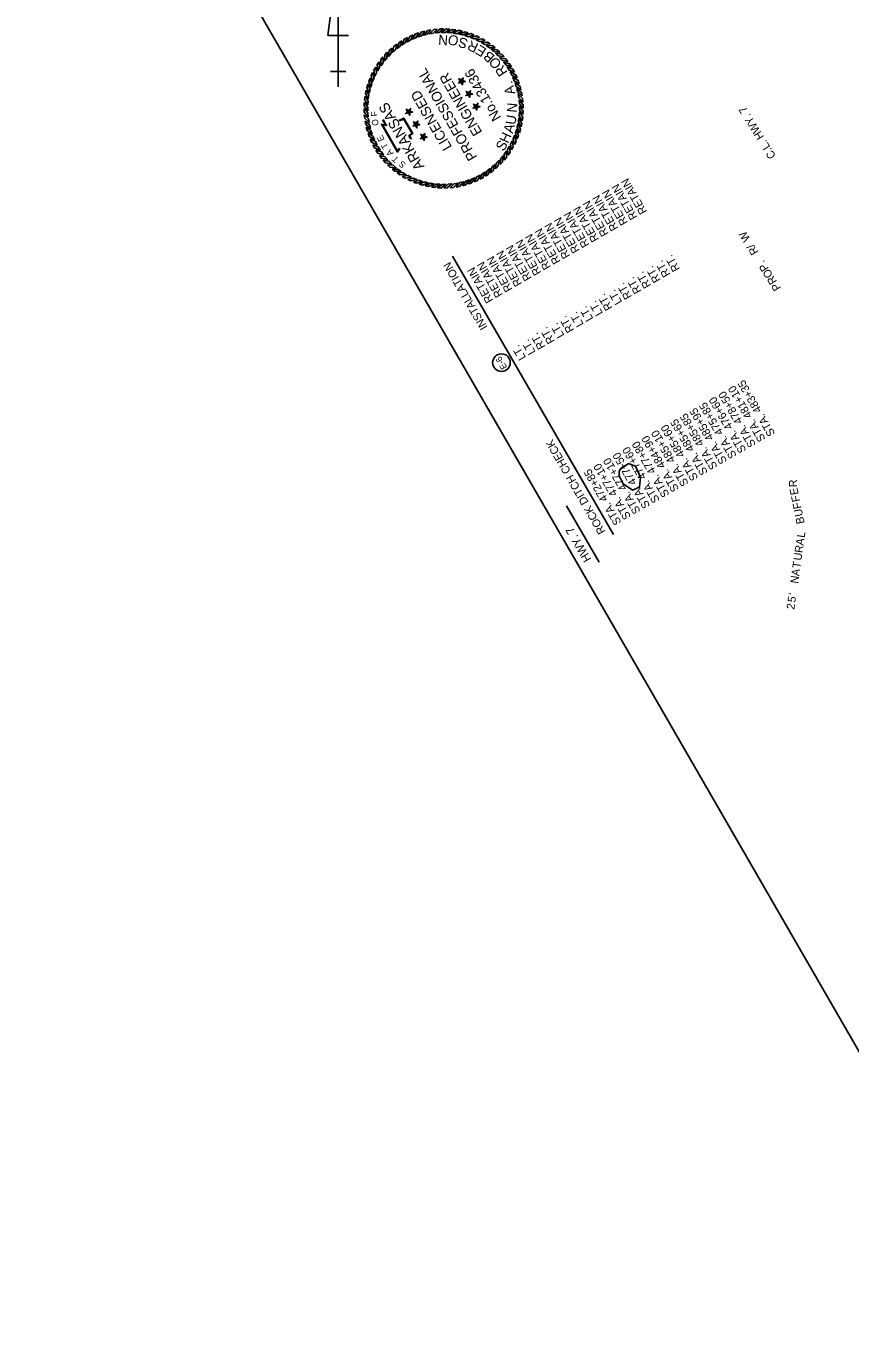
# Model space of a CAD drawing. Extents: x 956270 to 957915, y 1920520 to 1922423.
# Drawn here: x 956270 to 956888, y 1920520 to 1921493 of the extents above; entities that cross this region are included whole.
import ezdxf

# ---------------------------------------------------------------- set-up
doc = ezdxf.new("R2010")
doc.units = 0
for name, color, linetype in [('1', 7, 'Continuous'), ('44', 7, 'Continuous'), ('63', 7, 'Continuous'), ('G-ANNO-SYMB', 7, 'Continuous'), ('NO PLOT', 7, 'Continuous'), ('R_Draft', 7, 'Continuous'), ('S_TREE', 7, 'Continuous')]:
    doc.layers.add(name, color=color, linetype=linetype)

msp = doc.modelspace()

# ---------------------------------------------------------------- linework, layer by layer
at = {"layer": '1'}
msp.add_circle((956626.82, 1921240.31), 6.61, dxfattribs=at)
at = {"layer": '44'}
for p, q in [((956710.7, 1921111.49), (956590.2, 1921320.21)), ((956700.07, 1921090.71), (956675.65, 1921133)), ((956700.07, 1921090.71), (956675.65, 1921133))]:
    msp.add_line(p, q, dxfattribs=at)
at = {"layer": '63'}
for p, q in [((956504.33, 1921547.02), (956496.64, 1921485.48)), ((956504.33, 1921447.02), (956504.33, 1921547.02)), ((956504.33, 1921547.02), (956504.33, 1921470.09)), ((956496.64, 1921485.48), (956512.03, 1921485.48)), ((956504.33, 1921447.02), (956504.33, 1921470.09)), ((956504.33, 1921458.55), (956498.57, 1921458.55)), ((956498.57, 1921458.55), (956510.1, 1921458.55)), ((956504.33, 1921447.02), (956504.33, 1921458.55))]:
    msp.add_line(p, q, dxfattribs=at)
at = {"layer": 'G-ANNO-SYMB'}
for points in [[(956556.23, 1921483.92), (956553.97, 1921482.7), (956552.26, 1921478.46), (956554.61, 1921479.92)], [(956560.48, 1921485.89), (956558.13, 1921484.85), (956556.09, 1921480.76), (956558.55, 1921482.03)], [(956564.87, 1921487.52), (956562.45, 1921486.67), (956560.09, 1921482.75), (956562.65, 1921483.82)], [(956569.37, 1921488.8), (956566.89, 1921488.14), (956564.24, 1921484.42), (956566.87, 1921485.29)], [(956573.97, 1921489.73), (956571.44, 1921489.26), (956568.5, 1921485.76), (956571.19, 1921486.42)], [(956578.62, 1921490.29), (956576.06, 1921490.03), (956572.86, 1921486.76), (956575.59, 1921487.21)], [(956583.3, 1921490.48), (956580.73, 1921490.42), (956577.28, 1921487.42), (956580.04, 1921487.65)], [(956587.98, 1921490.31), (956585.42, 1921490.45), (956581.74, 1921487.73), (956584.51, 1921487.75)], [(956592.63, 1921489.77), (956590.09, 1921490.11), (956586.21, 1921487.69), (956588.98, 1921487.49)], [(956597.23, 1921488.87), (956594.72, 1921489.41), (956590.66, 1921487.3), (956593.4, 1921486.88)], [(956601.74, 1921487.61), (956599.28, 1921488.34), (956595.07, 1921486.56), (956597.77, 1921485.92)], [(956606.14, 1921486), (956603.75, 1921486.92), (956599.41, 1921485.47), (956602.05, 1921484.63)], [(956610.4, 1921484.05), (956608.08, 1921485.16), (956603.65, 1921484.05), (956606.21, 1921483)], [(956614.49, 1921481.77), (956612.27, 1921483.05), (956607.76, 1921482.3), (956610.24, 1921481.06)], [(956544.59, 1921476.1), (956542.68, 1921474.38), (956542, 1921469.86), (956543.95, 1921471.83)], [(956548.26, 1921479), (956546.22, 1921477.45), (956545.19, 1921472.99), (956547.29, 1921474.8)], [(956552.15, 1921481.62), (956549.99, 1921480.22), (956548.62, 1921475.86), (956550.85, 1921477.5)], [(956618.39, 1921479.17), (956616.28, 1921480.63), (956611.73, 1921480.23), (956614.1, 1921478.8)], [(956622.08, 1921476.28), (956620.09, 1921477.9), (956615.51, 1921477.86), (956617.77, 1921476.24)], [(956625.52, 1921473.11), (956623.67, 1921474.88), (956619.11, 1921475.2), (956621.22, 1921473.41)], [(956535.09, 1921465.77), (956533.63, 1921463.66), (956534.03, 1921459.11), (956535.47, 1921461.48)], [(956537.98, 1921469.46), (956536.36, 1921467.47), (956536.4, 1921462.9), (956538.02, 1921465.15)], [(956541.15, 1921472.91), (956539.38, 1921471.05), (956539.06, 1921466.49), (956540.85, 1921468.61)], [(956628.71, 1921469.68), (956627, 1921471.59), (956622.48, 1921472.26), (956624.45, 1921470.32)], [(956631.62, 1921466.01), (956630.06, 1921468.05), (956625.61, 1921469.07), (956627.42, 1921466.98)], [(956634.23, 1921462.12), (956632.84, 1921464.27), (956628.48, 1921465.65), (956630.12, 1921463.41)], [(956530.22, 1921457.78), (956529.11, 1921455.47), (956530.22, 1921451.03), (956531.26, 1921453.6)], [(956532.5, 1921461.87), (956531.21, 1921459.65), (956531.96, 1921455.14), (956533.21, 1921457.62)], [(956636.53, 1921458.04), (956635.31, 1921460.29), (956631.07, 1921462.01), (956632.53, 1921459.65)], [(956638.5, 1921453.79), (956637.47, 1921456.13), (956633.37, 1921458.17), (956634.65, 1921455.71)], [(956640.14, 1921449.4), (956639.28, 1921451.82), (956635.37, 1921454.17), (956636.44, 1921451.62)], [(956525.4, 1921444.61), (956524.86, 1921442.1), (956526.97, 1921438.05), (956527.39, 1921440.79)], [(956526.66, 1921449.12), (956525.92, 1921446.66), (956527.71, 1921442.46), (956528.34, 1921445.15)], [(956528.27, 1921453.52), (956527.34, 1921451.13), (956528.79, 1921446.79), (956529.64, 1921449.43)], [(956596.97, 1921451.23), (956595.94, 1921451.34), (956594.61, 1921449.87), (956596.55, 1921450.28)], [(956596.97, 1921451.23), (956596.76, 1921452.25), (956594.95, 1921453.06), (956595.94, 1921451.34)], [(956596.97, 1921451.23), (956596.55, 1921450.28), (956597.54, 1921448.57), (956597.75, 1921450.54)], [(956596.97, 1921451.23), (956597.88, 1921451.76), (956598.08, 1921453.73), (956596.76, 1921452.25)], [(956596.97, 1921451.23), (956597.75, 1921450.54), (956599.69, 1921450.95), (956597.88, 1921451.76)], [(956602.43, 1921441.79), (956603.33, 1921442.31), (956603.54, 1921444.28), (956602.21, 1921442.81)], [(956641.42, 1921444.89), (956640.76, 1921447.37), (956637.04, 1921450.03), (956637.91, 1921447.39)], [(956642.34, 1921440.3), (956641.88, 1921442.82), (956638.38, 1921445.76), (956639.04, 1921443.07)], [(956523.95, 1921435.36), (956523.81, 1921432.8), (956526.53, 1921429.12), (956526.52, 1921431.9)], [(956524.49, 1921440.01), (956524.15, 1921437.47), (956526.58, 1921433.59), (956526.78, 1921436.36)], [(956602.43, 1921441.79), (956601.39, 1921441.9), (956600.07, 1921440.42), (956602, 1921440.83)], [(956602.43, 1921441.79), (956602.21, 1921442.81), (956600.4, 1921443.61), (956601.39, 1921441.9)], [(956602.43, 1921441.79), (956602, 1921440.83), (956603, 1921439.12), (956603.2, 1921441.09)], [(956602.43, 1921441.79), (956603.2, 1921441.09), (956605.14, 1921441.5), (956603.33, 1921442.31)], [(956607.88, 1921432.34), (956608.79, 1921432.86), (956608.99, 1921434.83), (956607.67, 1921433.36)], [(956642.9, 1921435.65), (956642.64, 1921438.2), (956639.38, 1921441.4), (956639.83, 1921438.67)], [(956643.1, 1921430.97), (956643.04, 1921433.53), (956640.04, 1921436.98), (956640.27, 1921434.22)], [(956523.78, 1921430.68), (956523.84, 1921428.12), (956526.84, 1921424.66), (956526.61, 1921427.43)], [(956523.98, 1921426), (956524.24, 1921423.45), (956527.5, 1921420.24), (956527.05, 1921422.98)], [(956557.41, 1921428.39), (956556.38, 1921428.5), (956555.05, 1921427.03), (956556.99, 1921427.44)], [(956557.41, 1921428.39), (956557.2, 1921429.41), (956555.39, 1921430.22), (956556.38, 1921428.5)], [(956557.41, 1921428.39), (956556.99, 1921427.44), (956557.98, 1921425.73), (956558.19, 1921427.7)], [(956557.41, 1921428.39), (956558.31, 1921428.91), (956558.52, 1921430.88), (956557.2, 1921429.41)], [(956557.41, 1921428.39), (956558.19, 1921427.7), (956560.12, 1921428.11), (956558.31, 1921428.91)], [(956607.88, 1921432.34), (956606.85, 1921432.45), (956605.52, 1921430.98), (956607.46, 1921431.39)], [(956607.88, 1921432.34), (956607.67, 1921433.36), (956605.86, 1921434.16), (956606.85, 1921432.45)], [(956607.88, 1921432.34), (956607.46, 1921431.39), (956608.45, 1921429.67), (956608.66, 1921431.64)], [(956607.88, 1921432.34), (956608.66, 1921431.64), (956610.6, 1921432.05), (956608.79, 1921432.86)], [(956642.39, 1921421.63), (956642.73, 1921424.18), (956640.31, 1921428.05), (956640.1, 1921425.29)], [(956642.93, 1921426.29), (956643.07, 1921428.85), (956640.35, 1921432.52), (956640.36, 1921429.75)], [(956524.54, 1921421.35), (956525, 1921418.83), (956528.5, 1921415.89), (956527.84, 1921418.58)], [(956525.46, 1921416.76), (956526.12, 1921414.28), (956529.84, 1921411.62), (956528.97, 1921414.25)], [(956562.87, 1921418.95), (956561.83, 1921419.05), (956560.5, 1921417.58), (956562.44, 1921417.99)], [(956562.87, 1921418.95), (956562.65, 1921419.96), (956560.84, 1921420.77), (956561.83, 1921419.05)], [(956562.87, 1921418.95), (956562.44, 1921417.99), (956563.43, 1921416.28), (956563.64, 1921418.25)], [(956562.87, 1921418.95), (956563.77, 1921419.47), (956563.98, 1921421.44), (956562.65, 1921419.96)], [(956562.87, 1921418.95), (956563.64, 1921418.25), (956565.58, 1921418.66), (956563.77, 1921419.47)], [(956640.22, 1921412.52), (956640.96, 1921414.98), (956639.17, 1921419.19), (956638.54, 1921416.49)], [(956641.48, 1921417.04), (956642.02, 1921419.54), (956639.91, 1921423.6), (956639.49, 1921420.86)], [(956526.75, 1921412.25), (956527.6, 1921409.83), (956531.52, 1921407.48), (956530.44, 1921410.03)], [(956528.38, 1921407.86), (956529.42, 1921405.51), (956533.51, 1921403.47), (956532.24, 1921405.94)], [(956568.32, 1921409.5), (956567.29, 1921409.61), (956565.96, 1921408.13), (956567.9, 1921408.55)], [(956568.32, 1921409.5), (956568.1, 1921410.52), (956566.29, 1921411.32), (956567.29, 1921409.61)], [(956568.32, 1921409.5), (956567.9, 1921408.55), (956568.89, 1921406.83), (956569.1, 1921408.8)], [(956568.32, 1921409.5), (956569.22, 1921410.02), (956569.43, 1921411.99), (956568.1, 1921410.52)], [(956568.32, 1921409.5), (956569.1, 1921408.8), (956571.03, 1921409.21), (956569.22, 1921410.02)], [(956634.38, 1921399.77), (956635.67, 1921401.99), (956634.92, 1921406.5), (956633.67, 1921404.03)], [(956636.66, 1921403.87), (956637.77, 1921406.18), (956636.67, 1921410.62), (956635.62, 1921408.05)], [(956638.61, 1921408.13), (956639.54, 1921410.52), (956638.09, 1921414.86), (956637.25, 1921412.21)], [(956530.35, 1921403.61), (956531.57, 1921401.35), (956535.81, 1921399.64), (956534.35, 1921402)], [(956532.65, 1921399.53), (956534.04, 1921397.37), (956538.4, 1921396), (956536.76, 1921398.23)], [(956535.26, 1921395.64), (956536.82, 1921393.6), (956541.27, 1921392.57), (956539.46, 1921394.67)], [(956628.9, 1921392.19), (956630.52, 1921394.18), (956630.48, 1921398.75), (956628.86, 1921396.5)], [(956631.79, 1921395.87), (956633.25, 1921397.98), (956632.85, 1921402.54), (956631.41, 1921400.17)], [(956538.17, 1921391.97), (956539.88, 1921390.06), (956544.4, 1921389.38), (956542.43, 1921391.33)], [(956541.36, 1921388.54), (956543.21, 1921386.77), (956547.78, 1921386.45), (956545.66, 1921388.24)], [(956614.73, 1921380.03), (956616.89, 1921381.42), (956618.26, 1921385.78), (956616.03, 1921384.14)], [(956618.62, 1921382.64), (956620.66, 1921384.2), (956621.69, 1921388.66), (956619.59, 1921386.84)], [(956622.3, 1921385.55), (956624.21, 1921387.26), (956624.88, 1921391.79), (956622.93, 1921389.82)], [(956625.73, 1921388.74), (956627.5, 1921390.6), (956627.82, 1921395.16), (956626.03, 1921393.04)], [(956544.8, 1921385.37), (956546.79, 1921383.75), (956551.37, 1921383.79), (956549.12, 1921385.4)], [(956548.49, 1921382.47), (956550.6, 1921381.02), (956555.16, 1921381.41), (956552.78, 1921382.85)], [(956552.39, 1921379.88), (956554.61, 1921378.59), (956559.12, 1921379.35), (956556.64, 1921380.59)], [(956556.48, 1921377.6), (956558.8, 1921376.49), (956563.23, 1921377.6), (956560.67, 1921378.64)], [(956560.74, 1921375.65), (956563.14, 1921374.73), (956567.47, 1921376.18), (956564.83, 1921377.02)], [(956597.51, 1921372.85), (956599.99, 1921373.5), (956602.64, 1921377.23), (956600.01, 1921376.36)], [(956602.01, 1921374.13), (956604.43, 1921374.98), (956606.79, 1921378.9), (956604.23, 1921377.82)], [(956606.4, 1921375.76), (956608.75, 1921376.8), (956610.79, 1921380.89), (956608.33, 1921379.62)], [(956610.65, 1921377.73), (956612.91, 1921378.95), (956614.62, 1921383.19), (956612.27, 1921381.73)], [(956565.14, 1921374.04), (956567.6, 1921373.31), (956571.81, 1921375.09), (956569.11, 1921375.72)], [(956569.65, 1921372.78), (956572.16, 1921372.24), (956576.22, 1921374.35), (956573.48, 1921374.77)], [(956574.25, 1921371.88), (956576.79, 1921371.54), (956580.67, 1921373.96), (956577.91, 1921374.16)], [(956578.9, 1921371.34), (956581.46, 1921371.2), (956585.14, 1921373.92), (956582.37, 1921373.9)], [(956583.58, 1921371.16), (956586.15, 1921371.23), (956589.6, 1921374.23), (956586.84, 1921373.99)], [(956588.26, 1921371.36), (956590.82, 1921371.62), (956594.02, 1921374.88), (956591.29, 1921374.43)], [(956592.92, 1921371.92), (956595.44, 1921372.38), (956598.38, 1921375.89), (956595.69, 1921375.22)]]:
    msp.add_lwpolyline(points, close=True, dxfattribs=at)
for points in [[(956550.72, 1921400.9), (956548.81, 1921398.19), (956536.76, 1921419.02), (956539.96, 1921418.54), (956539.12, 1921419.95), (956538.42, 1921421.12), (956537.87, 1921422.38)], [(956550.41, 1921401.12), (956548.84, 1921398.89), (956537.49, 1921418.52), (956540.7, 1921418.04), (956539.45, 1921420.14), (956538.76, 1921421.29), (956538.22, 1921422.53)], [(956549.88, 1921421.93), (956550.49, 1921421.7), (956551.13, 1921421.87), (956552.33, 1921422.4), (956553.46, 1921423.05), (956559.79, 1921412.08), (956558.18, 1921411.14), (956557.5, 1921410.75), (956557.71, 1921409.87), (956558.59, 1921408.34), (956558.4, 1921407.97)], [(956550.01, 1921422.29), (956550.51, 1921422.1), (956551.01, 1921422.23), (956552.16, 1921422.74), (956553.6, 1921423.57), (956560.31, 1921411.94), (956558.37, 1921410.81), (956557.94, 1921410.57), (956558.07, 1921410.01), (956559.02, 1921408.36), (956558.74, 1921407.8)]]:
    msp.add_lwpolyline(points, dxfattribs=at)
at = {"layer": 'NO PLOT'}
msp.add_lwpolyline([(957012.51, 1920520.44), (956420.48, 1921545.87), (956463.26, 1921570.57), (956365.36, 1921740.14), (956378, 1921747.44), (956270.25, 1921934.07), (956666.17, 1922162.65), (956816.66, 1921901.98), (956749.98, 1921863.48), (956962.48, 1921495.42), (957029.16, 1921533.92), (957172.25, 1921286.08), (957120.9, 1921256.43), (957292.23, 1920959.68), (957343.58, 1920989.33), (957463.85, 1920781.02)], close=True, dxfattribs=at)
msp.add_lwpolyline([(957012.51, 1920520.44), (956420.48, 1921545.87), (956463.26, 1921570.57), (956365.36, 1921740.14), (956378, 1921747.44), (956270.25, 1921934.07), (956666.17, 1922162.65), (956816.66, 1921901.98), (956749.98, 1921863.48), (956962.48, 1921495.42), (957029.16, 1921533.92), (957172.25, 1921286.08), (957120.9, 1921256.43), (957292.23, 1920959.68), (957343.58, 1920989.33), (957463.85, 1920781.02)], close=True, dxfattribs=at)
msp.add_lwpolyline([(957012.51, 1920520.44), (956420.48, 1921545.87), (956463.26, 1921570.57), (956365.36, 1921740.14), (956378, 1921747.44), (956270.25, 1921934.07), (956666.17, 1922162.65), (956816.66, 1921901.98), (956749.98, 1921863.48), (956962.48, 1921495.42), (957029.16, 1921533.92), (957172.25, 1921286.08), (957120.9, 1921256.43), (957292.23, 1920959.68), (957343.58, 1920989.33), (957463.85, 1920781.02)], close=True, dxfattribs=at)
msp.add_lwpolyline([(957012.51, 1920520.44), (956420.48, 1921545.87), (956463.26, 1921570.57), (956365.36, 1921740.14), (956378, 1921747.44), (956270.25, 1921934.07), (956666.17, 1922162.65), (956816.66, 1921901.98), (956749.98, 1921863.48), (956962.48, 1921495.42), (957029.16, 1921533.92), (957172.25, 1921286.08), (957120.9, 1921256.43), (957292.23, 1920959.68), (957343.58, 1920989.33), (957463.85, 1920781.02)], close=True, dxfattribs=at)
msp.add_lwpolyline([(957012.51, 1920520.44), (956420.48, 1921545.87), (956463.26, 1921570.57), (956365.36, 1921740.14), (956378, 1921747.44), (956270.25, 1921934.07), (956666.17, 1922162.65), (956816.66, 1921901.98), (956749.98, 1921863.48), (956962.48, 1921495.42), (957029.16, 1921533.92), (957172.25, 1921286.08), (957120.9, 1921256.43), (957292.23, 1920959.68), (957343.58, 1920989.33), (957463.85, 1920781.02)], close=True, dxfattribs=at)
msp.add_lwpolyline([(957012.51, 1920520.44), (956420.48, 1921545.87), (956463.26, 1921570.57), (956365.36, 1921740.14), (956378, 1921747.44), (956270.25, 1921934.07), (956666.17, 1922162.65), (956816.66, 1921901.98), (956749.98, 1921863.48), (956962.48, 1921495.42), (957029.16, 1921533.92), (957172.25, 1921286.08), (957120.9, 1921256.43), (957292.23, 1920959.68), (957343.58, 1920989.33), (957463.85, 1920781.02)], close=True, dxfattribs=at)
at = {"layer": 'S_TREE'}
msp.add_lwpolyline([(956715.37, 1921159.9), (956722.12, 1921164.63), (956727.35, 1921162.78), (956731, 1921154.46), (956730.38, 1921146.86), (956724.98, 1921144.61), (956717.97, 1921149.35), (956715.03, 1921155.38), (956714.99, 1921159.08), (956715.96, 1921160.49)], dxfattribs=at)

# ---------------------------------------------------------------- texts
at = {"layer": '1'}
msp.add_text('E-6 ', height=4.8, rotation=120, dxfattribs=at).set_placement((956631.23, 1921236.85))
at = {"layer": '44'}
for s, height, p in [('RETAIN', 6, (956736.14, 1921353.6)), ('RETAIN', 6, (956721.74, 1921345.29)), ('RETAIN', 6, (956728.96, 1921349.45)), ('RETAIN', 6, (956700.09, 1921332.79)), ('RETAIN', 6, (956707.35, 1921336.98)), ('RETAIN', 6, (956714.53, 1921341.12)), ('RETAIN', 6, (956685.7, 1921324.48)), ('RETAIN', 6, (956692.91, 1921328.64)), ('RETAIN', 6, (956671.3, 1921316.17)), ('RETAIN', 6, (956678.48, 1921320.31)), ('RETAIN', 6, (956649.65, 1921303.67)), ('RETAIN', 6, (956656.87, 1921307.83)), ('RETAIN', 6, (956664.05, 1921311.98)), ('RETAIN', 6, (956635.26, 1921295.36)), ('RETAIN', 6, (956642.44, 1921299.5)), ('RT.', 6, (956760.83, 1921310.59)), ('INSTALLATION', 6, (956616.62, 1921266.92)), ('RETAIN', 6, (956620.83, 1921287.02)), ('RETAIN', 6, (956628.04, 1921291.19)), ('RT.', 6, (956739.18, 1921298.09)), ('RT.', 6, (956746.39, 1921302.26)), ('RT.', 6, (956753.61, 1921306.42)), ('RT.', 6, (956724.78, 1921289.78)), ('RT.', 6, (956732, 1921293.94)), ('RT.', 6, (956710.35, 1921281.45)), ('LT.', 6, (956717.49, 1921285.73)), ('LT.', 6, (956695.88, 1921273.26)), ('LT.', 6, (956703.06, 1921277.4)), ('LT.', 6, (956674.24, 1921260.76)), ('RT.', 6, (956681.52, 1921264.8)), ('LT.', 6, (956688.67, 1921269.09)), ('RT.', 6, (956659.91, 1921252.32)), ('RT.', 6, (956667.09, 1921256.47)), ('LT.', 6, (956645.41, 1921244.12)), ('LT.', 6, (956652.62, 1921248.28)), ('STA. 481+10', 6, (956825.02, 1921183.03)), ('STA. 483+35', 6, (956832.24, 1921187.19)), ('STA. 476+60', 6, (956810.59, 1921174.69)), ('STA. 478+50', 6, (956817.81, 1921178.86)), ('STA. 485+85', 6, (956788.98, 1921162.22)), ('STA. 485+95', 6, (956796.19, 1921166.38)), ('STA. 475+85', 6, (956803.41, 1921170.55)), ('STA. 485+60', 6, (956774.55, 1921153.88)), ('STA. 485+65', 6, (956781.76, 1921158.05)), ('ROCK DITCH CHECK', 6, (956705.05, 1921113.76)), ('STA. 484+90', 6, (956760.15, 1921145.57)), ('STA. 485+10', 6, (956767.37, 1921149.74)), ('STA. 477+50', 6, (956738.5, 1921133.07)), ('STA. 477+60', 6, (956745.72, 1921137.24)), ('STA. 477+80', 6, (956752.93, 1921141.41)), ('STA. 477+10', 6, (956724.11, 1921124.76)), ('STA. 477+10', 6, (956731.32, 1921128.93)), ('STA. 472+85', 6, (956716.89, 1921120.6)), ('HWY. 7', 6.25, (956694.38, 1921093.01)), ('HWY. 7', 6.25, (956694.38, 1921093.01))]:
    msp.add_text(s, height=height, rotation=120, dxfattribs=at).set_placement(p)
at = {"layer": 'G-ANNO-SYMB'}
for s, height, rotation, p in [('N', 7.5, 176.10067, (956586.93, 1921485.65)), ('O', 7.5, 164.77573, (956595.38, 1921484.52)), ('S', 7.5, 163.48784, (956602.26, 1921482.54)), ('R', 7.5, 155.65967, (956610.13, 1921479.12)), ('E', 7.5, 147.83149, (956616.17, 1921475.29)), ('B', 7.5, 138.88501, (956622.31, 1921470.09)), ('O', 7.5, 131.42961, (956627.44, 1921464.37)), ('R', 7.5, 123.22866, (956631.7, 1921457.97)), ('PROFESSIONAL', 7.5, 120, (956608.83, 1921394.35)), ('ENGINEER', 7.5, 120, (956612.55, 1921412.99)), ('No.13436', 7.47, 120, (956626.85, 1921423.98)), ('A', 7.5, 103.09908, (956637.27, 1921442.05)), ('.', 7.5, 111.30002, (956635.48, 1921449.53)), ('ARKANSAS', 7.747, 120, (956569.24, 1921387.27)), ('LICENSED', 7.5, 120, (956589.93, 1921401.99)), ('N', 7.5, 84.93262, (956638.24, 1921427.51)), ('F', 4.75, 95.36282, (956533.89, 1921425.12)), ('U', 7.5, 80.90262, (956637.18, 1921418.17)), ('O', 4.75, 101.2218, (956534.92, 1921418.33)), ('A', 7.5, 73.44722, (956635.28, 1921411.68)), ('E', 4.75, 116.67203, (956539.28, 1921407.53)), ('S', 7.5, 58.16364, (956628.35, 1921398.23)), ('H', 7.5, 65.61905, (956631.73, 1921404.13)), ('T', 4.75, 121.47887, (956542.19, 1921402.2)), ('A', 4.75, 128.67877, (956546.07, 1921397.36)), ('T', 4.75, 136.90148, (956550.26, 1921393.13)), ('S', 4.75, 139.77256, (956555.62, 1921389.25))]:
    msp.add_text(s, height=height, rotation=rotation, dxfattribs=at).set_placement(p)
at = {"layer": 'R_Draft'}
for s, rotation, p in [('C.L. HWY. 7', 121.71363, (956832.82, 1921395.21)), ('W', 122.05288, (956813.6, 1921333.05)), ('/', 122.05288, (956816.71, 1921328.09)), ('R', 122.05288, (956819.72, 1921323.28)), ('P', 122.05288, (956827.46, 1921310.91)), ('.', 122.05288, (956824.46, 1921315.71)), ('O', 122.05288, (956830.57, 1921305.94)), ('R', 122.05288, (956833.58, 1921301.14)), ('P', 122.05288, (956836.59, 1921296.33)), ('R', 92.10778, (956848.49, 1921147.03)), ('E', 101.55546, (956849.68, 1921141.77)), ('F', 101.55546, (956850.76, 1921136.49)), ('F', 101.55546, (956851.84, 1921131.22)), ('U', 101.55546, (956852.99, 1921125.57)), ('B', 101.55546, (956854.13, 1921120.02)), ('A', 81.81509, (956853.27, 1921102.99)), ('L', 81.81509, (956854.11, 1921108.79)), ('U', 81.81509, (956851.64, 1921091.68)), ('R', 81.81509, (956852.46, 1921097.38)), ('A', 81.81509, (956849.98, 1921080.08)), ('T', 81.81509, (956850.81, 1921085.88)), ('N', 81.81509, (956849.17, 1921074.47)), ('5', 81.81509, (956847.13, 1921060.3)), ("'", 81.81509, (956847.9, 1921065.63)), ('2', 81.81509, (956846.36, 1921054.97))]:
    msp.add_text(s, height=6, rotation=rotation, dxfattribs=at).set_placement(p)

doc.saveas('drawing.dxf')
